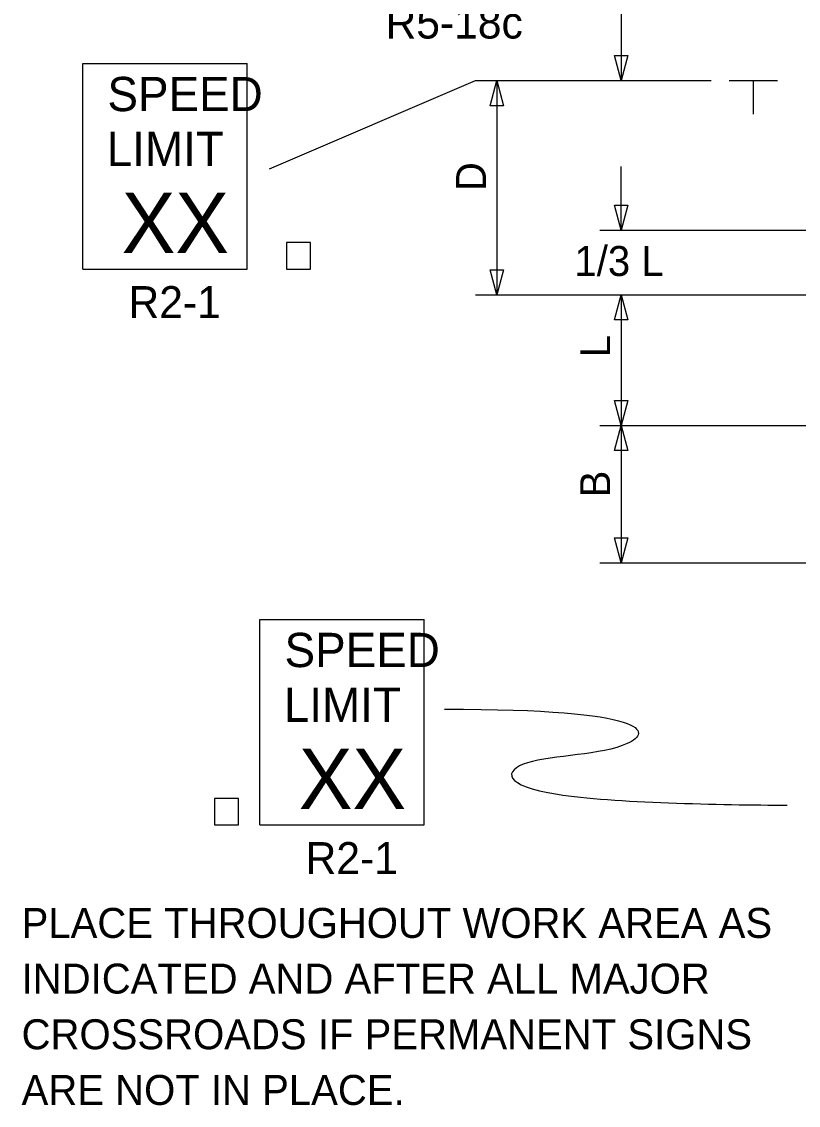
# Model space of a CAD drawing. Extents: x 16732 to 18475, y 6994 to 8262.
# Drawn here: x 16732.3 to 16913.7, y 7787.9 to 8040.9 of the extents above; entities that cross this region are included whole.
import ezdxf

# ---------------------------------------------------------------- set-up
doc = ezdxf.new("R2010")
doc.units = 0
doc.layers.add('TRAFFIC_SIGNS_PR', color=7, linetype='Continuous')
doc.layers.add('TYPICAL_TEXT_DIMEN_PR', color=7, linetype='Continuous')

msp = doc.modelspace()

# ---------------------------------------------------------------- linework, layer by layer
at = {"layer": 'TRAFFIC_SIGNS_PR'}
for p, q in [((16746.58, 8031.16), (16784.98, 8031.16)), ((16746.58, 7983.16), (16746.58, 8031.16)), ((16784.98, 7983.16), (16784.98, 8031.16)), ((16746.58, 7983.16), (16784.98, 7983.16)), ((16787.94, 7901.34), (16826.34, 7901.34)), ((16787.94, 7853.34), (16787.94, 7901.34)), ((16826.34, 7853.34), (16826.34, 7901.34)), ((16787.94, 7853.34), (16826.34, 7853.34))]:
    msp.add_line(p, q, dxfattribs=at)
for points in [[(16794.14, 7983.16), (16799.74, 7983.16), (16799.74, 7989.33), (16794.14, 7989.33)], [(16777.33, 7853.34), (16782.92, 7853.34), (16782.92, 7859.51), (16777.33, 7859.51)]]:
    msp.add_lwpolyline(points, close=True, dxfattribs=at)
at = {"layer": 'TYPICAL_TEXT_DIMEN_PR'}
for p, q in [((16872.31, 8067.14), (16872.31, 8027.14)), ((16872.31, 8027.14), (16870.74, 8033)), ((16870.74, 8033), (16872.31, 8033)), ((16872.31, 8033), (16873.88, 8033)), ((16873.88, 8033), (16872.31, 8027.14)), ((16790.23, 8006.52), (16838.31, 8027.14)), ((16838.31, 8027.14), (16893.31, 8027.14)), ((16841.74, 8021.27), (16843.31, 8027.14)), ((16843.31, 8027.14), (16843.31, 7977.14)), ((16843.31, 8027.14), (16844.88, 8021.27)), ((16897.56, 8027.14), (16908.81, 8027.14)), ((16903.18, 8027.14), (16903.18, 8019.35)), ((16843.31, 8021.27), (16841.74, 8021.27)), ((16844.88, 8021.27), (16843.31, 8021.27)), ((16872.31, 7992.2), (16872.31, 8007.13)), ((16872.31, 7992.2), (16870.74, 7998.07)), ((16870.74, 7998.07), (16872.31, 7998.07)), ((16872.31, 7998.07), (16873.88, 7998.07)), ((16873.88, 7998.07), (16872.31, 7992.2)), ((16867.31, 7992.2), (17020.91, 7992.2)), ((16843.31, 7977.14), (16841.74, 7983)), ((16841.74, 7983), (16843.31, 7983)), ((16843.31, 7983), (16844.88, 7983)), ((16844.88, 7983), (16843.31, 7977.14)), ((16838.31, 7977.14), (16999.07, 7977.14)), ((16870.74, 7971.27), (16872.31, 7977.14)), ((16872.31, 7977.14), (16873.88, 7971.27)), ((16872.31, 7977.14), (16872.31, 7946.61)), ((16872.31, 7971.27), (16870.74, 7971.27)), ((16873.88, 7971.27), (16872.31, 7971.27)), ((16872.31, 7946.61), (16870.74, 7952.47)), ((16870.74, 7952.47), (16872.31, 7952.47)), ((16872.31, 7952.47), (16873.88, 7952.47)), ((16873.88, 7952.47), (16872.31, 7946.61)), ((16867.31, 7946.61), (16973.56, 7946.61)), ((16870.74, 7940.75), (16872.31, 7946.61)), ((16872.31, 7946.61), (16872.31, 7914.55)), ((16872.31, 7946.61), (16873.88, 7940.75)), ((16872.31, 7940.75), (16870.74, 7940.75)), ((16873.88, 7940.75), (16872.31, 7940.75)), ((16872.31, 7914.55), (16870.74, 7920.41)), ((16870.74, 7920.41), (16872.31, 7920.41)), ((16872.31, 7920.41), (16873.88, 7920.41)), ((16873.88, 7920.41), (16872.31, 7914.55)), ((16867.31, 7914.55), (16973.56, 7914.55))]:
    msp.add_line(p, q, dxfattribs=at)
msp.add_open_spline([(16831.09, 7880.39), (16879.55, 7880.39), (16879.55, 7869.64), (16844.64, 7869.64), (16844.64, 7858.92), (16895.95, 7858.04), (16911.08, 7857.94)], degree=3, dxfattribs=at)

# ---------------------------------------------------------------- texts
at = {"layer": 'TRAFFIC_SIGNS_PR'}
for s, height, p in [('R5-18c', 7.44, (16817.28, 8036.98)), ('SPEED', 8, (16752.35, 8020.02)), ('LIMIT', 8, (16752.19, 8007.22)), ('XX', 14.031, (16755.69, 7986.92)), ('R2-1', 7.44, (16757.26, 7971.72)), ('SPEED', 8, (16793.71, 7890.2)), ('LIMIT', 8, (16793.54, 7877.4)), ('XX', 14.031, (16797.05, 7857.09)), ('R2-1', 7.44, (16798.62, 7841.89)), ('PLACE THROUGHOUT WORK AREA AS', 7, (16732.3, 7826.96)), ('INDICATED AND AFTER ALL MAJOR', 7, (16732.3, 7813.96)), ('CROSSROADS IF PERMANENT SIGNS', 7, (16732.3, 7800.96)), ('ARE NOT IN PLACE.', 7, (16732.3, 7787.96))]:
    msp.add_text(s, height=height, dxfattribs=at).set_placement(p)
at = {"layer": 'TYPICAL_TEXT_DIMEN_PR'}
for s, p in [('D', (16840.75, 8001.35)), ('L', (16869.75, 7962.52)), ('B', (16869.75, 7929.82))]:
    msp.add_text(s, height=7, rotation=90, dxfattribs=at).set_placement(p)
msp.add_text('1/3 L', height=7, dxfattribs=at).set_placement((16861.41, 7981.53))

doc.saveas('drawing.dxf')
